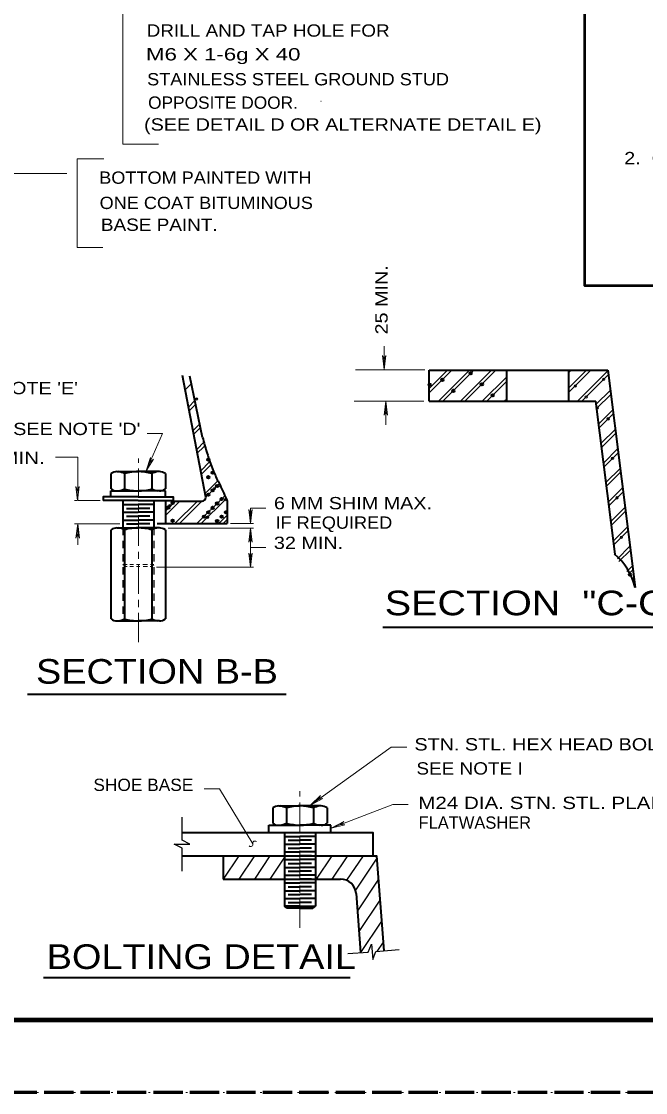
# Model space of a CAD drawing. Extents: x 312583 to 312854, y 144419 to 144597.
# Drawn here: x 312760.8 to 312799.3, y 144418.6 to 144484.7 of the extents above; entities that cross this region are included whole.
import ezdxf

# ---------------------------------------------------------------- set-up
doc = ezdxf.new("R2010")
doc.units = 0
doc.header["$LTSCALE"] = 0.3
doc.header["$PDMODE"] = 32
doc.header["$PDSIZE"] = 0.15
for name, pattern in [('DOTTED', [1.5, 0.3, -1.2]), ('LONG_DASH_SHORT_DASH', [9.9, 6, -1.2, 1.5, -1.2]), ('LONG_DASHED', [7.5, 6, -1.5]), ('SHORT_DASHED', [2.7, 1.5, -1.2])]:
    doc.linetypes.add(name, pattern=pattern)
for name, color, linetype, lineweight in [('1', 7, 'Continuous', 40), ('2', 7, 'Continuous', 13), ('62', 7, 'DOTTED', 13), ('63', 7, 'LONG_DASHED', 60)]:
    doc.layers.add(name, color=color, linetype=linetype, lineweight=lineweight)

msp = doc.modelspace()

# ---------------------------------------------------------------- linework, layer by layer
at = {"layer": '1'}
for p, q in [((312772.1817, 144455.3588), (312770.7404, 144462.8645)), ((312771.9747, 144459.0542), (312771.2004, 144462.8338)), ((312794.5913, 144463.0825), (312794.714, 144463.1975)), ((312796.991, 144463.1975), (312798.6777, 144449.7808)), ((312790.6813, 144461.2808), (312790.758, 144461.3575)), ((312766.6924, 144456.9458), (312768.0034, 144456.9458)), ((312769.3144, 144456.9458), (312768.0034, 144456.9458)), ((312766.3244, 144456.8232), (312766.3244, 144455.8648)), ((312767.1677, 144456.8232), (312767.1677, 144455.8648)), ((312768.839, 144456.8232), (312768.839, 144455.8648)), ((312769.6824, 144456.8232), (312769.6824, 144455.8648)), ((312766.3244, 144455.7498), (312768.0034, 144455.7498)), ((312766.3244, 144455.3818), (312766.3244, 144455.7422)), ((312769.6824, 144455.7498), (312768.0034, 144455.7498)), ((312769.6824, 144455.3818), (312769.6824, 144455.7422)), ((312768.0034, 144455.1442), (312765.849, 144455.1442)), ((312767.045, 144455.1442), (312767.045, 144453.4652)), ((312767.045, 144454.9065), (312768.0034, 144454.9065)), ((312768.0034, 144455.1442), (312770.1577, 144455.1442)), ((312768.9617, 144454.9065), (312768.0034, 144454.9065)), ((312768.9617, 144455.1442), (312768.9617, 144453.4652)), ((312769.6824, 144455.1442), (312769.6824, 144453.7488)), ((312770.1577, 144455.1212), (312771.944, 144455.1212)), ((312773.5004, 144455.1212), (312773.5004, 144453.7258)), ((312767.045, 144454.4235), (312768.0034, 144454.4235)), ((312767.2827, 144454.6688), (312768.0034, 144454.6688)), ((312768.724, 144454.6688), (312768.0034, 144454.6688)), ((312768.9617, 144454.4235), (312768.0034, 144454.4235)), ((312767.045, 144453.9482), (312768.0034, 144453.9482)), ((312767.2827, 144454.1858), (312768.0034, 144454.1858)), ((312767.2827, 144453.7105), (312768.0034, 144453.7105)), ((312768.724, 144454.1858), (312768.0034, 144454.1858)), ((312768.9617, 144453.9482), (312768.0034, 144453.9482)), ((312768.724, 144453.7105), (312768.0034, 144453.7105)), ((312769.184, 144453.7258), (312773.5004, 144453.7258)), ((312766.3244, 144453.3502), (312766.3244, 144447.8378)), ((312766.6924, 144453.4652), (312768.0034, 144453.4652)), ((312767.1677, 144453.3502), (312767.1677, 144447.8378)), ((312769.3144, 144453.4652), (312768.0034, 144453.4652)), ((312768.839, 144453.3502), (312768.839, 144447.8378)), ((312769.6824, 144453.3502), (312769.6824, 144447.8378)), ((312798.5703, 144450.0108), (312798.647, 144450.0108)), ((312798.67, 144449.8038), (312798.6777, 144449.8115)), ((312766.6924, 144447.7152), (312768.0034, 144447.7152)), ((312769.3144, 144447.7152), (312768.0034, 144447.7152)), ((312776.3078, 144436.1756), (312776.3078, 144435.2173)), ((312776.6758, 144436.2906), (312777.9868, 144436.2906)), ((312777.1511, 144436.1756), (312777.1511, 144435.2173)), ((312779.2978, 144436.2906), (312777.9868, 144436.2906)), ((312778.8225, 144436.1756), (312778.8225, 144435.2173)), ((312779.6658, 144436.1756), (312779.6658, 144435.2173)), ((312776.0701, 144434.6423), (312776.0701, 144435.0946)), ((312776.0701, 144435.0946), (312777.9868, 144435.0946)), ((312779.9035, 144435.0946), (312777.9868, 144435.0946)), ((312779.9035, 144434.6423), (312779.9035, 144435.0946)), ((312777.0285, 144434.6423), (312777.0285, 144430.0959)), ((312777.0285, 144434.4046), (312777.9868, 144434.4046)), ((312778.9451, 144434.4046), (312777.9868, 144434.4046)), ((312778.9451, 144434.6423), (312778.9451, 144430.0959)), ((312777.0285, 144433.9293), (312777.9868, 144433.9293)), ((312777.2661, 144434.1669), (312777.9868, 144434.1669)), ((312778.7075, 144434.1669), (312777.9868, 144434.1669)), ((312778.9451, 144433.9293), (312777.9868, 144433.9293)), ((312777.0285, 144433.4463), (312777.9868, 144433.4463)), ((312777.2661, 144433.6839), (312777.9868, 144433.6839)), ((312777.2661, 144433.2086), (312777.9868, 144433.2086)), ((312778.7075, 144433.6839), (312777.9868, 144433.6839)), ((312778.9451, 144433.4463), (312777.9868, 144433.4463)), ((312778.7075, 144433.2086), (312777.9868, 144433.2086)), ((312777.0285, 144432.9709), (312777.9868, 144432.9709)), ((312777.0285, 144432.4879), (312777.9868, 144432.4879)), ((312777.2661, 144432.7256), (312777.9868, 144432.7256)), ((312778.9451, 144432.9709), (312777.9868, 144432.9709)), ((312778.7075, 144432.7256), (312777.9868, 144432.7256)), ((312778.9451, 144432.4879), (312777.9868, 144432.4879)), ((312777.0285, 144432.0126), (312777.9868, 144432.0126)), ((312777.2661, 144432.2503), (312777.9868, 144432.2503)), ((312777.2661, 144431.7673), (312777.9868, 144431.7673)), ((312778.7075, 144432.2503), (312777.9868, 144432.2503)), ((312778.9451, 144432.0126), (312777.9868, 144432.0126)), ((312778.7075, 144431.7673), (312777.9868, 144431.7673)), ((312777.0285, 144431.5296), (312777.9868, 144431.5296)), ((312777.2661, 144431.2919), (312777.9868, 144431.2919)), ((312778.9451, 144431.5296), (312777.9868, 144431.5296)), ((312778.7075, 144431.2919), (312777.9868, 144431.2919)), ((312777.0285, 144431.0543), (312777.9868, 144431.0543)), ((312777.0285, 144430.5713), (312777.9868, 144430.5713)), ((312777.2661, 144430.8089), (312777.9868, 144430.8089)), ((312778.9451, 144431.0543), (312777.9868, 144431.0543)), ((312778.7075, 144430.8089), (312777.9868, 144430.8089)), ((312778.9451, 144430.5713), (312777.9868, 144430.5713)), ((312777.9868, 144430.0959), (312777.0285, 144430.0959)), ((312777.2048, 144429.9733), (312777.0285, 144430.0959)), ((312777.9868, 144429.9733), (312777.2048, 144429.9733)), ((312777.2661, 144430.3336), (312777.9868, 144430.3336)), ((312778.7075, 144430.3336), (312777.9868, 144430.3336)), ((312777.9868, 144430.0959), (312778.9451, 144430.0959)), ((312777.9868, 144429.9733), (312778.7765, 144429.9733)), ((312778.7765, 144429.9733), (312778.9451, 144430.0959))]:
    msp.add_line(p, q, dxfattribs=at)
at = {"layer": '1', "lineweight": 13}
for p, q in [((312785.9663, 144461.8021), (312787.3693, 144463.1975)), ((312785.9663, 144463.1515), (312786.0123, 144463.1975)), ((312785.9663, 144462.0705), (312787.0933, 144463.1975)), ((312786.5337, 144461.2808), (312788.4503, 144463.1975)), ((312786.8097, 144461.2808), (312788.7187, 144463.1975)), ((312787.8907, 144461.2808), (312789.8073, 144463.1975)), ((312788.159, 144461.2808), (312790.0757, 144463.1975)), ((312789.2477, 144461.2808), (312790.758, 144462.7911)), ((312789.516, 144461.2808), (312790.758, 144462.5228)), ((312790.597, 144461.2808), (312790.758, 144461.4418)), ((312769.7514, 144453.7488), (312769.6824, 144453.8178)), ((312767.3134, 144451.1958), (312767.045, 144451.1958)), ((312767.3287, 144451.0732), (312767.2214, 144451.0732)), ((312767.7197, 144451.1958), (312767.4897, 144451.1958)), ((312767.7197, 144451.0732), (312767.4897, 144451.0732)), ((312768.0034, 144451.1958), (312767.8884, 144451.1958)), ((312768.0034, 144451.0732), (312767.9037, 144451.0732)), ((312768.0034, 144451.1958), (312768.103, 144451.1958)), ((312768.0034, 144451.0732), (312768.0954, 144451.0732)), ((312768.2947, 144451.1958), (312768.5784, 144451.1958)), ((312768.31, 144451.0732), (312768.5784, 144451.0732)), ((312768.7394, 144451.0732), (312768.793, 144451.0732)), ((312768.7624, 144451.1958), (312768.9617, 144451.1958))]:
    msp.add_line(p, q, dxfattribs=at)
at = {"layer": '1', "linetype": 'LONG_DASH_SHORT_DASH', "lineweight": 13}
for p, q in [((312768.0187, 144446.4118), (312768.0187, 144457.7432)), ((312777.9868, 144428.7696), (312777.9868, 144437.2029))]:
    msp.add_line(p, q, dxfattribs=at)
at = {"layer": '1', "linetype": 'SHORT_DASHED', "lineweight": 25}
for p, q in [((312767.045, 144453.4652), (312767.045, 144447.7152)), ((312768.9617, 144453.4652), (312768.9617, 144447.7152)), ((312767.2214, 144451.0732), (312767.045, 144451.1958)), ((312768.793, 144451.0732), (312768.9617, 144451.1958))]:
    msp.add_line(p, q, dxfattribs=at)
at = {"layer": '1', "lineweight": 158}
msp.add_line((312616.5, 144423.0846), (312849, 144423.0846), dxfattribs=at)
at = {"layer": '1', "lineweight": 53}
msp.add_lwpolyline([(312849, 144468.4167), (312795.5728, 144468.4167), (312795.5728, 144585.0846)], dxfattribs=at)
at = {"layer": '1'}
for points in [[(312768.0034, 144455.3818), (312765.849, 144455.3818), (312765.849, 144455.1442)], [(312768.0034, 144455.3818), (312770.1577, 144455.3818), (312770.1577, 144455.1442)]]:
    msp.add_lwpolyline(points, dxfattribs=at)
for centre, radius, start, end in [((312766.7144, 144456.2487), 0.6917, 91.66257, 124.1297), ((312766.3804, 144455.0031), 1.9806, 66.63635, 78.22986), ((312768.091, 144453.3688), 3.5743, 91.405, 105.00202), ((312767.9157, 144453.3688), 3.5743, 74.99798, 88.595), ((312769.6264, 144455.0031), 1.9806, 101.77014, 113.36365), ((312769.2924, 144456.2487), 0.6917, 55.8703, 88.33743), ((312766.7144, 144456.4393), 0.6917, 235.8703, 268.33743), ((312766.3804, 144457.6849), 1.9806, 281.77014, 293.36365), ((312768.091, 144459.3192), 3.5743, 254.99798, 268.595), ((312767.9157, 144459.3192), 3.5743, 271.405, 285.00202), ((312769.6264, 144457.6849), 1.9806, 246.63635, 258.22986), ((312769.2924, 144456.4393), 0.6917, 271.66257, 304.1297), ((312771.9402, 144455.3569), 0.2396, 270, 0), ((312766.7144, 144452.7738), 0.6917, 91.66257, 124.1297), ((312766.3804, 144451.5282), 1.9806, 66.63635, 78.22986), ((312768.091, 144449.8938), 3.5743, 91.405, 105.00202), ((312767.9157, 144449.8938), 3.5743, 74.99798, 88.595), ((312769.6264, 144451.5282), 1.9806, 101.77014, 113.36365), ((312769.2924, 144452.7738), 0.6917, 55.8703, 88.33743), ((312794.9417, 144448.9083), 3.8346, 13.15231, 49.80612), ((312766.7144, 144448.4104), 0.6917, 235.8703, 268.33743), ((312766.3804, 144449.656), 1.9806, 281.77014, 293.36365), ((312768.091, 144451.2903), 3.5743, 254.99798, 268.595), ((312767.9157, 144451.2903), 3.5743, 271.405, 285.00202), ((312769.6264, 144449.656), 1.9806, 246.63635, 258.22986), ((312769.2924, 144448.4104), 0.6917, 271.66257, 304.1297), ((312776.6978, 144435.5992), 0.6917, 91.66257, 124.1297), ((312776.3638, 144434.3536), 1.9806, 66.63635, 78.22986), ((312778.0744, 144432.7193), 3.5743, 91.405, 105.00202), ((312777.8992, 144432.7193), 3.5743, 74.99798, 88.595), ((312779.6098, 144434.3536), 1.9806, 101.77014, 113.36365), ((312779.2758, 144435.5992), 0.6917, 55.8703, 88.33743), ((312776.6978, 144435.7898), 0.6917, 235.8703, 268.33743), ((312776.3638, 144437.0354), 1.9806, 281.77014, 293.36365), ((312778.0744, 144438.6698), 3.5743, 254.99798, 268.595), ((312777.8992, 144438.6698), 3.5743, 271.405, 285.00202), ((312779.6098, 144437.0354), 1.9806, 246.63635, 258.22986), ((312779.2758, 144435.7898), 0.6917, 271.66257, 304.1297)]:
    msp.add_arc(centre, radius, start, end, dxfattribs=at)
msp.add_spline([(312771.9747, 144459.0542), (312772.243, 144458.1188), (312772.726, 144456.7772), (312773.0557, 144456.1025), (312773.5004, 144455.1212)], degree=3, dxfattribs=at)
for p in [(312788.5347, 144463.0135), (312785.9893, 144462.3081), (312786.7713, 144462.6071), (312789.217, 144462.3311), (312787.4537, 144461.9248), (312789.8917, 144461.6565), (312772.335, 144457.6818), (312772.6034, 144456.8692), (312772.335, 144456.5932), (312772.335, 144455.5122), (312772.6034, 144455.7805), (312772.8794, 144456.0565), (312770.127, 144454.9985), (312772.8794, 144454.9678), (312773.1477, 144455.2438), (312769.8587, 144454.7225), (312772.0667, 144454.1552), (312772.335, 144454.4235), (312772.6034, 144454.6995), (312773.1477, 144454.1552), (312773.416, 144454.4235), (312770.127, 144453.9098), (312772.8794, 144453.8868), (312798.3557, 144450.5781)]:
    msp.add_point(p, dxfattribs=at)
at = {"layer": '2', "linetype": 'SHORT_DASHED', "lineweight": 25}
msp.add_line((312779.2975, 144479.7936), (312779.2821, 144479.7936), dxfattribs=at)
at = {"layer": '2'}
for p, q in [((312767.0538, 144477.1562), (312769.2618, 144477.1562)), ((312764.2328, 144470.7776), (312764.2328, 144476.2669)), ((312764.2328, 144476.2669), (312765.8888, 144476.2669)), ((312759.376, 144475.3546), (312763.6004, 144475.3546)), ((312764.2328, 144470.7776), (312765.8121, 144470.7776)), ((312783.1833, 144463.2128), (312783.1833, 144464.6771)), ((312783.076, 144464.1098), (312783.1833, 144463.8338)), ((312783.1833, 144463.2435), (312783.076, 144464.1098)), ((312783.2907, 144464.1098), (312783.1833, 144463.8338)), ((312783.1833, 144463.2435), (312783.2907, 144464.1098)), ((312781.4123, 144463.2281), (312785.7057, 144463.2281)), ((312794.5913, 144461.8405), (312795.9483, 144463.1975)), ((312794.5913, 144463.1975), (312794.599, 144463.1975)), ((312794.5913, 144462.1088), (312795.68, 144463.1975)), ((312795.1203, 144461.2808), (312796.991, 144463.1591)), ((312795.3887, 144461.2808), (312797.0217, 144462.9138)), ((312796.2857, 144461.0968), (312797.1443, 144461.9555)), ((312796.3163, 144460.8515), (312797.175, 144461.7101)), ((312781.3433, 144461.2885), (312785.6367, 144461.2885)), ((312783.2907, 144461.2808), (312783.1833, 144460.4145)), ((312783.2907, 144459.8318), (312783.2907, 144461.2885)), ((312783.2907, 144461.2808), (312783.398, 144460.4145)), ((312783.1833, 144460.4145), (312783.2907, 144460.6905)), ((312783.398, 144460.4145), (312783.2907, 144460.6905)), ((312796.439, 144459.8931), (312797.2977, 144460.7518)), ((312796.4697, 144459.6478), (312797.3283, 144460.5065)), ((312796.5923, 144458.6895), (312797.451, 144459.5481)), ((312796.623, 144458.4441), (312797.4817, 144459.3028)), ((312796.7457, 144457.4858), (312797.5967, 144458.3445)), ((312764.2697, 144457.8356), (312762.9052, 144457.8356)), ((312764.2697, 144455.1442), (312764.2697, 144457.8356)), ((312768.4864, 144456.9765), (312768.7547, 144457.8045)), ((312768.4864, 144456.9765), (312768.9464, 144457.7125)), ((312768.7547, 144457.8045), (312768.7394, 144457.5055)), ((312768.9464, 144457.7125), (312768.7394, 144457.5055)), ((312796.7687, 144457.2405), (312797.6273, 144458.0991)), ((312796.8913, 144456.2821), (312797.75, 144457.1408)), ((312796.922, 144456.0445), (312797.7807, 144456.8955)), ((312764.1547, 144456.0258), (312764.262, 144455.7498)), ((312764.262, 144455.1595), (312764.1547, 144456.0258)), ((312764.3694, 144456.0258), (312764.262, 144455.7498)), ((312764.262, 144455.1595), (312764.3694, 144456.0258)), ((312797.0447, 144455.0785), (312797.9033, 144455.9371)), ((312797.0753, 144454.8408), (312797.934, 144455.6918)), ((312764.078, 144455.1442), (312764.239, 144455.1442)), ((312764.2927, 144455.1442), (312765.6574, 144455.1442)), ((312774.8267, 144454.5922), (312774.934, 144454.3162)), ((312774.934, 144453.7258), (312774.8267, 144454.5922)), ((312774.934, 144453.7258), (312774.934, 144454.6842)), ((312775.8924, 144454.6842), (312774.934, 144454.6842)), ((312775.0414, 144454.5922), (312774.934, 144454.3162)), ((312774.934, 144453.7258), (312775.0414, 144454.5922)), ((312797.198, 144453.8748), (312798.0567, 144454.7335)), ((312797.2287, 144453.6371), (312798.0873, 144454.4881)), ((312764.078, 144453.7105), (312766.861, 144453.7105)), ((312764.2697, 144453.7028), (312764.1624, 144452.8365)), ((312764.2697, 144452.4148), (312764.2697, 144453.7028)), ((312764.2697, 144453.7028), (312764.377, 144452.8365)), ((312773.692, 144453.7258), (312775.1257, 144453.7258)), ((312764.1624, 144452.8365), (312764.2697, 144453.1125)), ((312764.377, 144452.8365), (312764.2697, 144453.1125)), ((312769.851, 144453.4422), (312775.1257, 144453.4422)), ((312774.934, 144453.4422), (312774.8267, 144452.5758)), ((312774.934, 144453.4422), (312774.8267, 144452.5758)), ((312774.934, 144451.0425), (312774.934, 144453.4422)), ((312774.934, 144453.4422), (312775.0414, 144452.5758)), ((312774.934, 144453.4422), (312775.0414, 144452.5758)), ((312797.3513, 144452.6711), (312798.21, 144453.5298)), ((312797.382, 144452.4335), (312798.2407, 144453.2845)), ((312774.8267, 144452.5758), (312774.934, 144452.8518)), ((312774.8267, 144452.5758), (312774.934, 144452.8518)), ((312775.0414, 144452.5758), (312774.934, 144452.8518)), ((312775.0414, 144452.5758), (312774.934, 144452.8518)), ((312774.934, 144452.2462), (312775.8847, 144452.2462)), ((312797.589, 144451.5518), (312798.3557, 144452.3261)), ((312774.8267, 144451.9088), (312774.934, 144451.6328)), ((312774.934, 144451.0425), (312774.8267, 144451.9088)), ((312774.8267, 144451.9088), (312774.934, 144451.6328)), ((312774.934, 144451.0425), (312774.8267, 144451.9088)), ((312775.0414, 144451.9088), (312774.934, 144451.6328)), ((312774.934, 144451.0425), (312775.0414, 144451.9088)), ((312775.0414, 144451.9088), (312774.934, 144451.6328)), ((312774.934, 144451.0425), (312775.0414, 144451.9088)), ((312797.681, 144451.3831), (312798.3863, 144452.0808)), ((312769.1304, 144451.0425), (312775.1257, 144451.0425)), ((312798.164, 144450.7698), (312798.509, 144451.1225)), ((312798.256, 144450.5935), (312798.5397, 144450.8771)), ((312798.624, 144449.8805), (312798.6623, 144449.9188)), ((312778.6308, 144436.3443), (312783.6295, 144439.9246)), ((312783.6295, 144439.9246), (312784.5878, 144439.9246)), ((312772.0681, 144437.3486), (312773.0265, 144437.3486)), ((312775.0811, 144433.9523), (312773.0265, 144437.3486)), ((312778.6308, 144436.3443), (312779.2671, 144436.9346)), ((312778.6308, 144436.3443), (312779.3975, 144436.7583)), ((312779.2671, 144436.9346), (312779.1061, 144436.6816)), ((312779.3975, 144436.7583), (312779.1061, 144436.6816)), ((312779.9188, 144434.9259), (312783.7138, 144436.3826)), ((312783.7138, 144436.3826), (312784.6721, 144436.3826)), ((312779.9188, 144434.9259), (312780.6931, 144435.3246)), ((312779.9188, 144434.9259), (312780.7621, 144435.1253)), ((312780.6931, 144435.3246), (312780.4708, 144435.1329)), ((312780.7621, 144435.1253), (312780.4708, 144435.1329))]:
    msp.add_line(p, q, dxfattribs=at)
at = {"layer": '2', "lineweight": 40}
for p, q in [((312785.9663, 144463.1975), (312796.991, 144463.1975)), ((312785.9663, 144461.2808), (312785.9663, 144463.1975)), ((312790.758, 144461.2808), (312790.758, 144463.1975)), ((312794.5913, 144461.2808), (312794.5913, 144463.1975)), ((312785.9663, 144461.2808), (312796.2627, 144461.2808)), ((312797.451, 144451.8431), (312796.2627, 144461.2808)), ((312783.1061, 144447.3258), (312801.9889, 144447.3258)), ((312761.1768, 144443.1886), (312777.1328, 144443.1886)), ((312773.2565, 144433.2086), (312773.2565, 144431.7673)), ((312773.2565, 144431.7673), (312780.5015, 144431.7673)), ((312781.4521, 144430.8856), (312781.7281, 144427.2286)), ((312762.1635, 144425.6879), (312781.093, 144425.6879))]:
    msp.add_line(p, q, dxfattribs=at)
at = {"layer": '2', "lineweight": 25}
for p, q in [((312770.9167, 144462.0058), (312771.2694, 144462.3508)), ((312771.1314, 144460.9478), (312771.484, 144461.3005)), ((312771.553, 144461.1012), (312771.185, 144460.7255)), ((312771.553, 144461.1012), (312771.553, 144461.0935)), ((312771.346, 144459.4298), (312771.829, 144459.9052)), ((312771.438, 144459.2458), (312771.829, 144459.6368)), ((312771.6297, 144458.0575), (312772.0667, 144458.4945)), ((312771.6374, 144458.3335), (312772.059, 144458.7552)), ((312771.8674, 144456.9918), (312772.4117, 144457.5438)), ((312772.5114, 144457.3675), (312771.898, 144456.7542)), ((312772.1817, 144455.3588), (312773.025, 144456.2098)), ((312772.1894, 144455.6425), (312772.9254, 144456.3785)), ((312770.5717, 144455.1058), (312769.667, 144454.2012)), ((312769.667, 144454.4695), (312770.2727, 144455.0752)), ((312770.2727, 144453.7258), (312771.6604, 144455.1135)), ((312770.5487, 144453.7258), (312771.9364, 144455.1135)), ((312771.6297, 144453.7258), (312773.3087, 144455.4048)), ((312771.898, 144453.7258), (312773.4084, 144455.2362)), ((312772.979, 144453.7258), (312773.5004, 144454.2395)), ((312773.255, 144453.7258), (312773.5004, 144453.9712)), ((312774.2148, 144433.2086), (312773.2565, 144431.7673)), ((312775.1731, 144433.2086), (312774.2148, 144431.7673)), ((312776.1315, 144433.2086), (312775.1731, 144431.7673)), ((312777.0285, 144433.1243), (312776.1315, 144431.7673)), ((312779.9571, 144433.2086), (312778.9988, 144431.7673)), ((312780.9231, 144433.2086), (312779.9648, 144431.7673)), ((312781.8815, 144433.2086), (312780.8695, 144431.6983)), ((312782.7325, 144433.0553), (312781.4215, 144431.0773)), ((312782.8321, 144431.7596), (312781.5365, 144429.8123)), ((312782.9241, 144430.4716), (312781.6285, 144428.5243)), ((312783.0238, 144429.1759), (312781.7281, 144427.2286)), ((312783.1235, 144427.8803), (312782.7325, 144427.3053))]:
    msp.add_line(p, q, dxfattribs=at)
at = {"layer": '2'}
for points in [[(312767.0538, 144477.1562), (312767.0538, 144485.5282), (312769.2158, 144485.5282)], [(312768.4864, 144456.9765), (312769.506, 144459.2842), (312768.5477, 144459.2842)]]:
    msp.add_lwpolyline(points, dxfattribs=at)
at = {"layer": '2', "lineweight": 25}
for points in [[(312770.7111, 144432.2503), (312770.7111, 144433.6839), (312770.2281, 144433.9293), (312771.1865, 144433.9293), (312770.7111, 144434.1669), (312770.7111, 144435.6006)], [(312780.9538, 144427.1749), (312782.2035, 144427.2669), (312782.4105, 144427.7576), (312782.4795, 144426.8069), (312782.6788, 144427.2976), (312784.1125, 144427.4126)]]:
    msp.add_lwpolyline(points, dxfattribs=at)
at = {"layer": '2', "lineweight": 40}
for points in [[(312770.7111, 144434.6423), (312782.4795, 144434.6423), (312782.4795, 144433.2086)], [(312770.7111, 144433.2086), (312782.7248, 144433.2086), (312783.1618, 144427.3359)]]:
    msp.add_lwpolyline(points, dxfattribs=at)
at = {"layer": '2'}
for centre, start, end in [((312774.951, 144433.9143), 226.06269, 16.06269), ((312775.2099, 144433.9889), 46.06269, 196.06269)]:
    msp.add_arc(centre, 0.1347, start, end, dxfattribs=at)
at = {"layer": '2', "lineweight": 40}
msp.add_arc((312780.4971, 144430.8109), 0.9583, 4.26806, 90, dxfattribs=at)
at = {"layer": '2'}
for p in [(312794.9823, 144462.2315), (312796.7457, 144462.6378), (312795.657, 144461.5491), (312771.6144, 144461.4232), (312796.3393, 144460.8745), (312797.014, 144460.1998), (312797.2823, 144457.7541), (312772.703, 144455.8878), (312769.9584, 144454.8298), (312773.3854, 144455.2055), (312797.5583, 144455.3161), (312772.2967, 144454.1245), (312797.8267, 144452.8781)]:
    msp.add_point(p, dxfattribs=at)
at = {"layer": '62'}
msp.add_lwpolyline([(312601.2, 144418.5846), (312853.5, 144418.5846), (312853.5, 144596.7846)], dxfattribs=at)
at = {"layer": '63'}
msp.add_line((312851.75, 144418.5846), (312583.526, 144418.5846), dxfattribs=at)

# ---------------------------------------------------------------- texts
at = {"layer": '2'}
for s, height, width, p in [('DRILL AND TAP HOLE FOR', 0.76, 1.15, (312768.5247, 144483.8022)), ('M6 X 1-6g X 40', 0.76, 1.35, (312768.4857, 144482.3342)), ('STAINLESS STEEL GROUND STUD', 0.76, 1.1, (312768.5548, 144480.7942)), ('OPPOSITE DOOR.', 0.76, 1.05, (312768.615, 144479.3481)), ('(SEE DETAIL D OR ALTERNATE DETAIL E)', 0.76, 1.2, (312768.3669, 144477.9997)), ('2.  CERTIFICATIONS SHALL BE FURNISHED THAT ALUMINUM ALLOY AND', 0.76, 1.2, (312798.0077, 144475.9219)), ('BOTTOM PAINTED WITH', 0.76, 1.1, (312765.5966, 144474.7154)), ('ONE COAT BITUMINOUS', 0.76, 1.1, (312765.6207, 144473.1572)), ('BASE PAINT.', 0.76, 1.15, (312765.7019, 144471.8069)), ("SEE NOTE 'E'", 0.76, 1.2, (312756.4963, 144461.7195)), ("SEE NOTE 'D'", 0.76, 1.2, (312760.2865, 144459.1961)), (' 20 MIN.', 0.76, 1.25, (312757.4344, 144457.4109)), ('6 MM SHIM MAX.', 0.76, 1.2, (312776.3841, 144454.6103)), ('IF REQUIRED', 0.76, 1.1, (312776.4817, 144453.4091)), ('32 MIN.', 0.76, 1.2, (312776.3822, 144452.1594)), ('SECTION  "C-C"', 1.52, 1.2, (312783.2242, 144448.0652)), ('SECTION B-B', 1.52, 1.15, (312761.6941, 144443.8389)), ('STN. STL. HEX HEAD BOLT', 0.76, 1.2, (312785.0563, 144439.7139)), ('SEE NOTE I', 0.76, 1.15, (312785.1798, 144438.2265)), ('SHOE BASE', 0.76, 1.05, (312765.2377, 144437.2121)), ('M24 DIA. STN. STL. PLAIN', 0.76, 1.25, (312785.2903, 144436.0971)), ('BOLTING DETAIL', 1.52, 1.15, (312762.3545, 144426.2207))]:
    msp.add_text(s, height=height, dxfattribs=dict(at, width=width)).set_placement(p)
at = {"layer": '2', "width": 1.2}
msp.add_text('25 MIN.', height=0.76, rotation=90, dxfattribs=at).set_placement((312783.4005, 144465.4118))
at = {"layer": '2'}
msp.add_text('FLATWASHER', height=0.76, dxfattribs=at).set_placement((312785.3114, 144434.8796))

doc.saveas('drawing.dxf')
